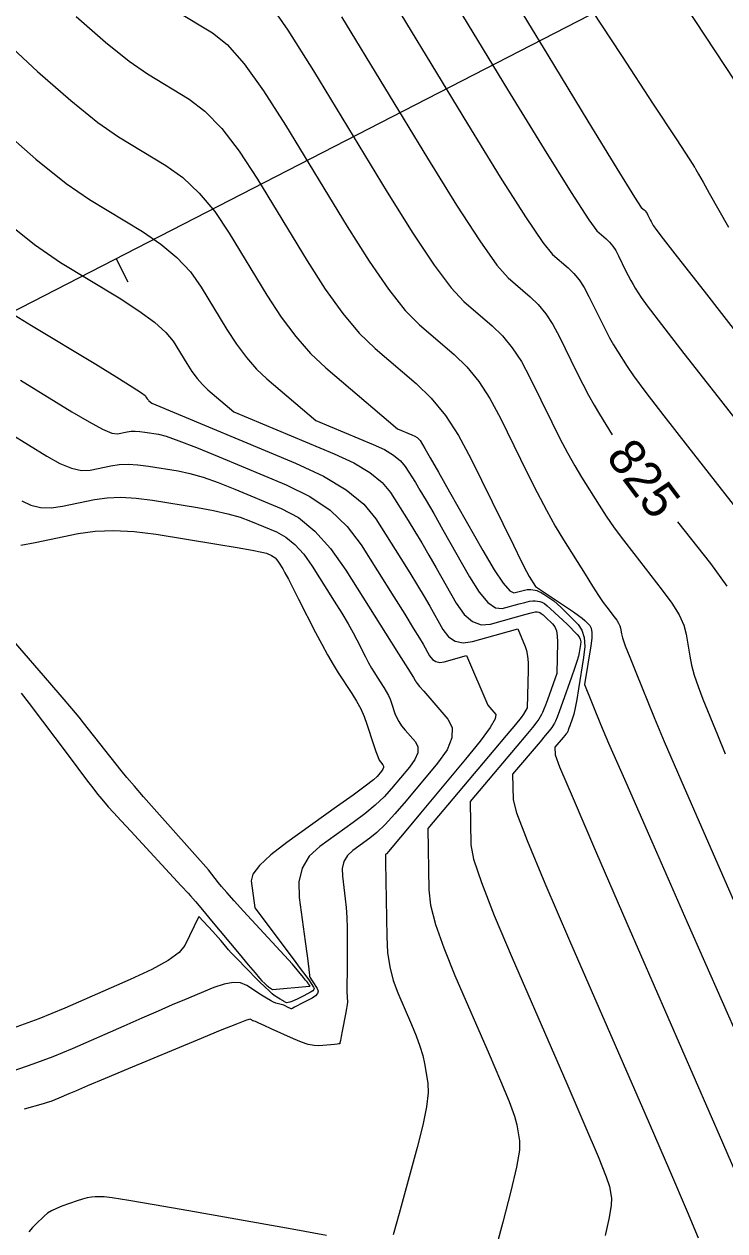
# Model space of a CAD drawing. Extents: x 1715724 to 1716561, y 394063 to 395906.
# Drawn here: x 1716008.73 to 1716035.77, y 394999.44 to 395046.03 of the extents above; entities that cross this region are included whole.
import ezdxf

# ---------------------------------------------------------------- set-up
doc = ezdxf.new("R2010")
doc.units = 0
for name, color, linetype in [('DT_X_Contour_Major', 7, 'Continuous'), ('DT_X_Contour_Minor', 7, 'Continuous'), ('GE_P_CL_10', 7, 'Continuous')]:
    doc.layers.add(name, color=color, linetype=linetype)

msp = doc.modelspace()

# ---------------------------------------------------------------- linework, layer by layer
at = {"layer": 'DT_X_Contour_Major'}
for points in [[(1716033.841, 395047.347), (1716036.153, 395043.821)], [(1716020.981, 395046.306), (1716024.291, 395040.859), (1716025.416, 395039.037), (1716026.311, 395037.658), (1716026.976, 395036.722), (1716027.41, 395036.229), (1716028.259, 395035.503), (1716028.569, 395035.203), (1716028.86, 395034.844), (1716029.133, 395034.427), (1716029.389, 395033.953), (1716030.046, 395032.611), (1716030.286, 395032.131), (1716030.513, 395031.698), (1716030.729, 395031.313), (1716030.932, 395030.974), (1716031.428, 395030.179)], [(1716007.741, 395042.079), (1716009.181, 395040.818), (1716010.351, 395039.875), (1716011.251, 395039.252), (1716013.293, 395038.016), (1716014.009, 395037.534), (1716014.626, 395037.016), (1716015.145, 395036.461), (1716015.564, 395035.87), (1716016.552, 395034.245), (1716016.926, 395033.668), (1716017.309, 395033.158), (1716017.7, 395032.714), (1716018.099, 395032.337), (1716019.981, 395030.73), (1716022.198, 395029.805), (1716022.632, 395029.603), (1716022.983, 395029.393), (1716023.253, 395029.174), (1716023.439, 395028.946), (1716023.828, 395028.329), (1716024.003, 395028.042), (1716024.239, 395027.642), (1716024.535, 395027.13), (1716024.891, 395026.506), (1716025.921, 395024.692), (1716026.289, 395024.105), (1716026.622, 395023.706), (1716026.919, 395023.493), (1716027.181, 395023.468), (1716027.831, 395023.649), (1716028.053, 395023.707), (1716028.231, 395023.746), (1716028.365, 395023.765), (1716028.455, 395023.765), (1716028.637, 395023.739), (1716028.714, 395023.714), (1716028.807, 395023.66), (1716028.918, 395023.575), (1716029.046, 395023.462), (1716029.683, 395022.861), (1716030.072, 395022.468), (1716030.143, 395022.38), (1716030.188, 395022.285), (1716030.208, 395022.183), (1716030.202, 395022.074), (1716030.153, 395021.774), (1716030.121, 395021.63), (1716030.06, 395021.422), (1716029.971, 395021.152), (1716029.854, 395020.818), (1716029.503, 395019.843), (1716029.385, 395019.519), (1716029.294, 395019.276), (1716029.231, 395019.116), (1716029.196, 395019.038), (1716029.138, 395018.938), (1716029.091, 395018.871), (1716028.992, 395018.747), (1716028.842, 395018.565), (1716028.64, 395018.324), (1716027.58, 395017.068), (1716027.596, 395016.078), (1716027.735, 395015.58), (1716028.145, 395014.51), (1716028.826, 395012.868), (1716029.778, 395010.655), (1716032.678, 395003.989), (1716033.631, 395001.789), (1716034.318, 395000.186), (1716034.738, 394999.181)], [(1716008.645, 395027.622), (1716008.985, 395027.46), (1716009.36, 395027.371), (1716009.77, 395027.357), (1716010.215, 395027.416), (1716011.447, 395027.672), (1716011.933, 395027.742), (1716012.467, 395027.762), (1716013.048, 395027.731), (1716013.678, 395027.65), (1716015.42, 395027.365), (1716016.038, 395027.251), (1716016.586, 395027.126), (1716017.064, 395026.989), (1716017.471, 395026.84), (1716018.464, 395026.427), (1716018.829, 395026.228), (1716019.181, 395025.941), (1716019.519, 395025.567), (1716019.844, 395025.106), (1716020.692, 395023.758), (1716020.985, 395023.285), (1716021.23, 395022.878), (1716021.426, 395022.536), (1716021.574, 395022.26), (1716021.903, 395021.609), (1716022.023, 395021.377), (1716022.138, 395021.168), (1716022.246, 395020.982), (1716022.348, 395020.82), (1716022.613, 395020.417), (1716022.706, 395020.266), (1716022.786, 395020.116), (1716022.854, 395019.966), (1716022.908, 395019.817), (1716023.037, 395019.42), (1716023.098, 395019.268), (1716023.184, 395019.11), (1716023.295, 395018.946), (1716023.431, 395018.776), (1716023.827, 395018.316), (1716023.924, 395018.126), (1716023.919, 395017.901), (1716023.813, 395017.642), (1716023.604, 395017.348), (1716022.911, 395016.516), (1716022.624, 395016.2), (1716022.281, 395015.876), (1716021.882, 395015.544), (1716021.428, 395015.203), (1716020.143, 395014.285), (1716019.732, 395013.903), (1716019.462, 395013.449), (1716019.334, 395012.921), (1716019.348, 395012.319), (1716019.573, 395010.618), (1716019.646, 395010.058), (1716019.699, 395009.656), (1716019.731, 395009.412), (1716019.741, 395009.324), (1716019.741, 395009.302), (1716019.741, 395009.293), (1716019.741, 395009.286), (1716019.742, 395009.279), (1716019.744, 395009.273), (1716019.748, 395009.257), (1716019.757, 395009.24), (1716019.781, 395009.2), (1716019.821, 395009.137), (1716019.875, 395009.052), (1716020.041, 395008.794), (1716020.076, 395008.699), (1716020.054, 395008.606), (1716019.975, 395008.517), (1716019.841, 395008.431), (1716019.408, 395008.205), (1716019.265, 395008.13), (1716019.161, 395008.076), (1716019.095, 395008.042), (1716019.068, 395008.028), (1716019.047, 395008.019), (1716019.034, 395008.018), (1716019.013, 395008.025), (1716018.984, 395008.037), (1716018.945, 395008.057), (1716018.746, 395008.163), (1716018.44, 395008.239), (1716018.356, 395008.27), (1716018.236, 395008.332), (1716018.079, 395008.424), (1716017.886, 395008.547), (1716017.322, 395008.915), (1716017.084, 395009.013), (1716016.792, 395009.032), (1716016.447, 395008.973), (1716016.047, 395008.835), (1716014.912, 395008.361), (1716014.446, 395008.165), (1716013.901, 395007.931), (1716013.275, 395007.659), (1716012.571, 395007.351), (1716010.585, 395006.477), (1716009.833, 395006.162), (1716009.068, 395005.873), (1716008.289, 395005.609)], [(1716033.949, 395026.821), (1716035.212, 395025.209), (1716035.852, 395024.335)]]:
    msp.add_lwpolyline(points, dxfattribs=at)
at = {"layer": 'DT_X_Contour_Minor'}
for points in [[(1716024.232, 395052.568), (1716028.934, 395044.827), (1716030.482, 395042.282), (1716031.6, 395040.455), (1716032.288, 395039.344), (1716032.545, 395038.949), (1716032.656, 395038.854), (1716032.697, 395038.815), (1716032.735, 395038.768), (1716032.771, 395038.713), (1716032.805, 395038.651), (1716032.891, 395038.474), (1716032.922, 395038.411), (1716032.952, 395038.354), (1716032.981, 395038.304), (1716033.007, 395038.259), (1716033.076, 395038.149), (1716033.304, 395037.851), (1716033.934, 395037.04), (1716034.968, 395035.716), (1716036.405, 395033.88)], [(1716023.148, 395050.481), (1716027.386, 395043.504), (1716028.794, 395041.201), (1716029.837, 395039.522), (1716030.517, 395038.47), (1716030.833, 395038.043), (1716031.191, 395037.737), (1716031.321, 395037.611), (1716031.443, 395037.46), (1716031.559, 395037.284), (1716031.666, 395037.085), (1716031.942, 395036.52), (1716032.044, 395036.318), (1716032.139, 395036.136), (1716032.23, 395035.973), (1716032.316, 395035.831), (1716032.537, 395035.477), (1716032.776, 395035.148), (1716033.327, 395034.427), (1716034.191, 395033.313), (1716035.367, 395031.807), (1716038.921, 395027.269)], [(1716028.03, 395050.528), (1716031.779, 395044.813), (1716033.01, 395042.937), (1716033.89, 395041.594), (1716034.42, 395040.786), (1716034.6, 395040.511), (1716034.611, 395040.49), (1716034.65, 395040.422), (1716034.756, 395040.234), (1716034.93, 395039.925), (1716035.172, 395039.496), (1716035.907, 395038.19)], [(1716022.065, 395048.394), (1716025.838, 395042.181), (1716027.105, 395040.119), (1716028.074, 395038.59), (1716028.746, 395037.596), (1716029.121, 395037.136), (1716029.725, 395036.62), (1716029.945, 395036.407), (1716030.152, 395036.152), (1716030.346, 395035.856), (1716030.527, 395035.519), (1716030.994, 395034.565), (1716031.165, 395034.225), (1716031.326, 395033.917), (1716031.479, 395033.643), (1716031.624, 395033.402), (1716031.997, 395032.805), (1716032.247, 395032.445), (1716032.72, 395031.813), (1716033.414, 395030.91), (1716034.329, 395029.735), (1716037.066, 395026.239)], [(1716018.08, 395046.985), (1716018.91, 395045.789), (1716019.898, 395044.219), (1716022.743, 395039.536), (1716023.728, 395037.955), (1716024.548, 395036.726), (1716025.205, 395035.848), (1716025.698, 395035.322), (1716026.793, 395034.387), (1716027.193, 395033.999), (1716027.568, 395033.536), (1716027.921, 395032.999), (1716028.25, 395032.387), (1716029.097, 395030.657), (1716029.407, 395030.038), (1716029.701, 395029.48), (1716029.978, 395028.982), (1716030.24, 395028.545), (1716030.917, 395027.461), (1716031.191, 395027.039), (1716031.505, 395026.586), (1716031.859, 395026.103), (1716032.253, 395025.59), (1716033.357, 395024.179), (1716033.726, 395023.677), (1716034.003, 395023.226), (1716034.189, 395022.828), (1716034.283, 395022.483), (1716034.414, 395021.63), (1716034.483, 395021.287), (1716034.592, 395020.894), (1716034.74, 395020.453), (1716034.928, 395019.964), (1716035.483, 395018.593), (1716035.789, 395017.864)], [(1716014.616, 395046.532), (1716015.995, 395045.697), (1716016.559, 395045.24), (1716017.217, 395044.493), (1716017.969, 395043.457), (1716018.814, 395042.132), (1716021.195, 395038.213), (1716022.039, 395036.873), (1716022.786, 395035.794), (1716023.435, 395034.974), (1716023.986, 395034.415), (1716025.328, 395033.27), (1716025.816, 395032.795), (1716026.277, 395032.228), (1716026.708, 395031.57), (1716027.112, 395030.821), (1716028.149, 395028.702), (1716028.528, 395027.944), (1716028.888, 395027.261), (1716029.228, 395026.652), (1716029.548, 395026.117), (1716030.377, 395024.789), (1716030.663, 395024.336), (1716030.898, 395023.973), (1716031.082, 395023.7), (1716031.215, 395023.517), (1716031.503, 395023.15), (1716031.599, 395023.019), (1716031.671, 395022.901), (1716031.719, 395022.798), (1716031.744, 395022.708), (1716031.778, 395022.486), (1716031.822, 395022.331), (1716031.93, 395022.033), (1716032.1, 395021.593), (1716032.334, 395021.009), (1716033.042, 395019.262), (1716033.432, 395018.332), (1716034.07, 395016.85), (1716034.957, 395014.818), (1716036.092, 395012.234)], [(1716010.743, 395046.321), (1716011.872, 395045.332), (1716012.789, 395044.594), (1716013.495, 395044.105), (1716015.094, 395043.137), (1716015.709, 395042.671), (1716016.353, 395042.001), (1716017.027, 395041.125), (1716017.731, 395040.045), (1716019.647, 395036.89), (1716020.35, 395035.792), (1716021.023, 395034.862), (1716021.664, 395034.101), (1716022.275, 395033.508), (1716023.862, 395032.153), (1716024.44, 395031.591), (1716024.985, 395030.92), (1716025.496, 395030.142), (1716025.973, 395029.255), (1716027.2, 395026.748), (1716027.609, 395025.915), (1716027.916, 395025.296), (1716028.121, 395024.892), (1716028.223, 395024.703), (1716028.461, 395024.321), (1716029.695, 395023.501), (1716029.935, 395023.338), (1716030.127, 395023.201), (1716030.271, 395023.09), (1716030.366, 395023.004), (1716030.557, 395022.812), (1716030.613, 395022.709), (1716030.638, 395022.544), (1716030.633, 395022.318), (1716030.596, 395022.029), (1716030.354, 395020.539), (1716030.978, 395018.999), (1716031.287, 395018.275), (1716031.944, 395016.766), (1716032.952, 395014.47), (1716034.308, 395011.387), (1716038.391, 395002.119)], [(1716007.717, 395045.61), (1716009.242, 395044.2), (1716010.526, 395043.075), (1716011.57, 395042.234), (1716012.373, 395041.679), (1716014.194, 395040.576), (1716014.859, 395040.103), (1716015.49, 395039.508), (1716016.086, 395038.793), (1716016.648, 395037.957), (1716018.099, 395035.567), (1716018.65, 395034.72), (1716019.213, 395033.97), (1716019.787, 395033.317), (1716020.374, 395032.762), (1716023.142, 395030.399), (1716023.698, 395030.167), (1716023.807, 395030.117), (1716023.895, 395030.064), (1716023.962, 395030.009), (1716024.009, 395029.952), (1716024.107, 395029.797), (1716024.199, 395029.64), (1716024.403, 395029.285), (1716024.719, 395028.731), (1716025.146, 395027.979), (1716026.435, 395025.709), (1716026.872, 395024.968), (1716027.217, 395024.448), (1716027.469, 395024.149), (1716027.63, 395024.07), (1716027.934, 395024.155), (1716028.042, 395024.182), (1716028.137, 395024.198), (1716028.219, 395024.204), (1716028.288, 395024.201), (1716028.455, 395024.176), (1716028.522, 395024.16), (1716028.599, 395024.129), (1716028.686, 395024.083), (1716028.783, 395024.023), (1716029.054, 395023.843), (1716029.166, 395023.761), (1716029.297, 395023.65), (1716029.449, 395023.509), (1716029.621, 395023.34), (1716030.106, 395022.851), (1716030.256, 395022.633), (1716030.342, 395022.348), (1716030.364, 395021.996), (1716030.322, 395021.576), (1716030.125, 395020.365), (1716030.055, 395019.954), (1716029.994, 395019.629), (1716029.942, 395019.39), (1716029.898, 395019.237), (1716029.793, 395018.945), (1716029.757, 395018.847), (1716029.73, 395018.774), (1716029.711, 395018.726), (1716029.701, 395018.703), (1716029.683, 395018.673), (1716029.669, 395018.653), (1716029.64, 395018.615), (1716029.594, 395018.561), (1716029.534, 395018.488), (1716029.215, 395018.111), (1716029.22, 395017.814), (1716029.394, 395017.361), (1716029.913, 395016.129), (1716030.778, 395014.118), (1716031.989, 395011.328), (1716035.677, 395002.85), (1716036.889, 395000.062)], [(1716007.835, 395038.56), (1716009.132, 395037.516), (1716010.13, 395036.825), (1716012.392, 395035.456), (1716013.159, 395034.966), (1716013.763, 395034.524), (1716014.203, 395034.129), (1716014.481, 395033.783), (1716015.004, 395032.922), (1716015.202, 395032.617), (1716015.405, 395032.346), (1716015.612, 395032.111), (1716015.823, 395031.911), (1716016.82, 395031.06), (1716020.698, 395029.444), (1716021.457, 395029.09), (1716022.072, 395028.721), (1716022.543, 395028.339), (1716022.87, 395027.941), (1716023.549, 395026.861), (1716023.808, 395026.443), (1716024.075, 395025.999), (1716024.352, 395025.529), (1716024.636, 395025.033), (1716025.407, 395023.675), (1716025.707, 395023.243), (1716026.027, 395022.964), (1716026.369, 395022.838), (1716026.732, 395022.865), (1716027.728, 395023.143), (1716028.058, 395023.233), (1716028.301, 395023.297), (1716028.457, 395023.334), (1716028.526, 395023.343), (1716028.594, 395023.333), (1716028.629, 395023.318), (1716028.683, 395023.28), (1716028.756, 395023.219), (1716028.848, 395023.134), (1716029.119, 395022.879), (1716029.207, 395022.763), (1716029.269, 395022.606), (1716029.304, 395022.408), (1716029.313, 395022.169), (1716029.291, 395020.961), (1716028.923, 395019.938), (1716028.849, 395019.738), (1716028.786, 395019.578), (1716028.733, 395019.456), (1716028.691, 395019.373), (1716028.593, 395019.203), (1716028.513, 395019.09), (1716028.345, 395018.879), (1716028.09, 395018.569), (1716027.747, 395018.16), (1716025.944, 395016.024), (1716025.972, 395014.342), (1716026.076, 395013.799), (1716026.376, 395012.891), (1716026.873, 395011.619), (1716027.567, 395009.982), (1716029.678, 395005.129), (1716030.374, 395003.515), (1716030.88, 395002.315), (1716031.195, 395001.527), (1716031.319, 395001.152), (1716031.396, 395000.703), (1716031.388, 395000.432), (1716031.305, 394999.954), (1716031.148, 394999.271)], [(1716008.182, 395034.903), (1716009.008, 395034.399), (1716011.491, 395032.895), (1716012.309, 395032.397), (1716012.899, 395032.031), (1716013.262, 395031.797), (1716013.397, 395031.695), (1716013.456, 395031.599), (1716013.478, 395031.565), (1716013.501, 395031.535), (1716013.524, 395031.508), (1716013.548, 395031.486), (1716013.659, 395031.391), (1716019.198, 395029.082), (1716020.282, 395028.576), (1716021.161, 395028.05), (1716021.833, 395027.503), (1716022.3, 395026.935), (1716023.27, 395025.393), (1716023.612, 395024.845), (1716023.912, 395024.356), (1716024.168, 395023.928), (1716024.381, 395023.56), (1716024.893, 395022.659), (1716025.108, 395022.376), (1716025.369, 395022.204), (1716025.675, 395022.143), (1716026.028, 395022.192), (1716027.78, 395022.68), (1716028.068, 395022.008), (1716028.121, 395021.842), (1716028.157, 395021.635), (1716028.176, 395021.386), (1716028.177, 395021.094), (1716028.145, 395019.635), (1716028.004, 395019.392), (1716027.91, 395019.266), (1716027.687, 395018.991), (1716027.334, 395018.568), (1716026.854, 395017.996), (1716024.309, 395014.981), (1716024.347, 395012.606), (1716024.416, 395012.018), (1716024.608, 395011.273), (1716024.921, 395010.369), (1716025.356, 395009.308), (1716026.678, 395006.268), (1716027.117, 395005.242), (1716027.442, 395004.444), (1716027.652, 395003.874), (1716027.749, 395003.531), (1716027.853, 395002.923), (1716027.842, 395002.555), (1716027.73, 395001.907), (1716027.517, 395000.981), (1716027.203, 394999.775), (1716026.233, 394996.186)], [(1716008.59, 395032.286), (1716010.569, 395031.067), (1716011.236, 395030.671), (1716011.753, 395030.396), (1716012.119, 395030.243), (1716012.335, 395030.211), (1716012.709, 395030.289), (1716012.857, 395030.31), (1716013.019, 395030.316), (1716013.196, 395030.307), (1716013.388, 395030.282), (1716013.918, 395030.195), (1716014.213, 395030.116), (1716014.701, 395029.944), (1716015.382, 395029.679), (1716016.256, 395029.321), (1716018.843, 395028.243), (1716019.752, 395027.795), (1716020.535, 395027.26), (1716021.195, 395026.638), (1716021.73, 395025.93), (1716022.991, 395023.925), (1716023.417, 395023.246), (1716023.748, 395022.714), (1716023.985, 395022.327), (1716024.127, 395022.087), (1716024.379, 395021.642), (1716024.486, 395021.502), (1716024.614, 395021.417), (1716024.766, 395021.387), (1716024.94, 395021.411), (1716025.806, 395021.652), (1716026.623, 395019.741), (1716026.936, 395019.377), (1716026.913, 395019.212), (1716026.71, 395018.87), (1716026.328, 395018.352), (1716025.767, 395017.658), (1716024.03, 395015.573), (1716023.458, 395014.888), (1716023.048, 395014.397), (1716022.798, 395014.1), (1716022.71, 395013.997), (1716022.687, 395013.981), (1716022.679, 395013.974), (1716022.675, 395013.966), (1716022.672, 395013.956), (1716022.673, 395013.946), (1716022.677, 395013.915), (1716022.678, 395013.901), (1716022.679, 395013.882), (1716022.679, 395013.858), (1716022.679, 395013.829), (1716022.678, 395013.681), (1716022.724, 395010.793), (1716022.758, 395010.194), (1716022.839, 395009.635), (1716022.968, 395009.115), (1716023.145, 395008.635), (1716023.679, 395007.407), (1716023.86, 395006.969), (1716024.004, 395006.573), (1716024.11, 395006.22), (1716024.178, 395005.91), (1716024.31, 395005.142), (1716024.321, 395004.77), (1716024.255, 395004.232), (1716024.112, 395003.528), (1716023.892, 395002.657), (1716023.204, 395000.112), (1716022.967, 394999.291)], [(1716008.187, 395030.22), (1716009.607, 395029.344), (1716010.111, 395029.065), (1716010.556, 395028.884), (1716010.944, 395028.8), (1716011.275, 395028.813), (1716012.078, 395028.98), (1716012.395, 395029.026), (1716012.743, 395029.039), (1716013.122, 395029.019), (1716013.533, 395028.966), (1716014.669, 395028.78), (1716015.126, 395028.684), (1716015.644, 395028.535), (1716016.223, 395028.334), (1716016.864, 395028.081), (1716018.654, 395027.335), (1716019.313, 395026.976), (1716019.947, 395026.459), (1716020.557, 395025.784), (1716021.143, 395024.952), (1716022.672, 395022.521), (1716023.174, 395021.723), (1716023.533, 395021.151), (1716023.75, 395020.806), (1716023.824, 395020.687), (1716023.832, 395020.672), (1716023.835, 395020.666), (1716023.837, 395020.662), (1716023.84, 395020.657), (1716023.842, 395020.653), (1716023.848, 395020.644), (1716023.851, 395020.641), (1716023.852, 395020.637), (1716023.854, 395020.634), (1716023.855, 395020.63), (1716023.858, 395020.621), (1716023.892, 395020.58), (1716023.99, 395020.464), (1716024.153, 395020.274), (1716024.381, 395020.009), (1716025.076, 395019.202), (1716025.247, 395018.869), (1716025.239, 395018.474), (1716025.051, 395018.019), (1716024.685, 395017.503), (1716023.47, 395016.045), (1716023.041, 395015.544), (1716022.664, 395015.137), (1716022.34, 395014.822), (1716022.069, 395014.6), (1716021.415, 395014.133), (1716021.206, 395013.939), (1716021.068, 395013.707), (1716021.003, 395013.438), (1716021.01, 395013.132), (1716021.125, 395012.267), (1716021.162, 395011.923), (1716021.187, 395011.542), (1716021.2, 395011.123), (1716021.202, 395010.667), (1716021.191, 395009.399), (1716021.188, 395008.981), (1716021.187, 395008.675), (1716021.19, 395008.482), (1716021.194, 395008.402), (1716021.211, 395008.34), (1716021.21, 395008.289), (1716021.197, 395008.183), (1716021.17, 395008.022), (1716021.129, 395007.806), (1716021.005, 395007.156), (1716020.963, 395006.942), (1716020.933, 395006.79), (1716020.915, 395006.697), (1716020.907, 395006.666), (1716020.903, 395006.662), (1716020.88, 395006.659), (1716020.816, 395006.653), (1716020.709, 395006.643), (1716020.56, 395006.631), (1716020.108, 395006.593), (1716019.919, 395006.598), (1716019.693, 395006.644), (1716019.429, 395006.73), (1716019.126, 395006.856), (1716018.269, 395007.246), (1716017.987, 395007.374), (1716017.781, 395007.467), (1716017.653, 395007.524), (1716017.602, 395007.545), (1716017.568, 395007.553), (1716017.554, 395007.557), (1716017.539, 395007.564), (1716017.522, 395007.573), (1716017.504, 395007.585), (1716017.452, 395007.618), (1716017.31, 395007.577), (1716016.923, 395007.429), (1716016.291, 395007.173), (1716015.413, 395006.809), (1716012.746, 395005.697), (1716011.853, 395005.324), (1716011.173, 395005.039), (1716010.706, 395004.843), (1716010.454, 395004.734), (1716010.064, 395004.563), (1716009.917, 395004.501), (1716009.766, 395004.444), (1716009.614, 395004.393), (1716009.458, 395004.346), (1716008.726, 395004.139)], [(1716008.596, 395025.914), (1716009.155, 395026.018), (1716010.816, 395026.363), (1716011.471, 395026.458), (1716012.19, 395026.485), (1716012.974, 395026.444), (1716013.823, 395026.334), (1716016.171, 395025.949), (1716016.951, 395025.819), (1716017.529, 395025.718), (1716017.905, 395025.644), (1716018.079, 395025.6), (1716018.274, 395025.519), (1716018.346, 395025.479), (1716018.415, 395025.423), (1716018.481, 395025.35), (1716018.545, 395025.259), (1716018.711, 395024.995), (1716018.796, 395024.848), (1716018.927, 395024.605), (1716019.103, 395024.266), (1716019.324, 395023.832), (1716019.974, 395022.547), (1716020.212, 395022.088), (1716020.438, 395021.675), (1716020.652, 395021.307), (1716020.854, 395020.986), (1716021.378, 395020.19), (1716021.561, 395019.892), (1716021.72, 395019.595), (1716021.853, 395019.299), (1716021.961, 395019.004), (1716022.216, 395018.218), (1716022.304, 395017.955), (1716022.377, 395017.755), (1716022.436, 395017.618), (1716022.48, 395017.544), (1716022.577, 395017.431), (1716022.601, 395017.384), (1716022.6, 395017.329), (1716022.574, 395017.265), (1716022.523, 395017.192), (1716022.352, 395016.988), (1716022.206, 395016.856), (1716021.897, 395016.616), (1716021.424, 395016.266), (1716020.787, 395015.807), (1716018.871, 395014.437), (1716018.246, 395013.959), (1716017.808, 395013.554), (1716017.557, 395013.22), (1716017.493, 395012.96), (1716017.632, 395011.911), (1716019.106, 395009.946), (1716019.387, 395009.571), (1716019.597, 395009.288), (1716019.737, 395009.097), (1716019.806, 395008.998), (1716019.897, 395008.856), (1716019.917, 395008.804), (1716019.908, 395008.755), (1716019.87, 395008.709), (1716019.802, 395008.665), (1716019.503, 395008.51), (1716019.423, 395008.469), (1716019.344, 395008.431), (1716019.266, 395008.394), (1716019.058, 395008.299), (1716018.986, 395008.27), (1716018.924, 395008.254), (1716018.873, 395008.252), (1716018.833, 395008.264), (1716018.741, 395008.313), (1716018.703, 395008.334), (1716018.607, 395008.392), (1716018.549, 395008.429), (1716018.385, 395008.535), (1716018.304, 395008.598), (1716018.182, 395008.706), (1716018.021, 395008.861), (1716017.819, 395009.061), (1716017.228, 395009.655), (1716017.024, 395009.862), (1716016.855, 395010.038), (1716016.721, 395010.183), (1716016.621, 395010.297), (1716016.404, 395010.558), (1716016.318, 395010.659), (1716016.224, 395010.767), (1716016.121, 395010.881), (1716016.011, 395011.001), (1716015.475, 395011.58), (1716014.935, 395010.456), (1716014.716, 395010.193), (1716014.29, 395009.887), (1716013.657, 395009.538), (1716012.818, 395009.145), (1716010.304, 395008.039), (1716009.299, 395007.625), (1716008.169, 395007.214)], [(1716011.023, 395019.061), (1716010.847, 395019.276), (1716010.572, 395019.604), (1716010.197, 395020.045), (1716009.721, 395020.599), (1716008.319, 395022.225)], [(1716008.617, 395020.198), (1716008.921, 395019.797), (1716010.425, 395017.801), (1716011.173, 395016.807), (1716011.323, 395016.61), (1716011.452, 395016.443), (1716011.56, 395016.306), (1716011.648, 395016.199), (1716011.854, 395015.955), (1716011.974, 395015.819), (1716012.179, 395015.593), (1716012.469, 395015.277), (1716012.845, 395014.871), (1716014.796, 395012.765), (1716015.055, 395012.486), (1716015.153, 395012.374), (1716015.337, 395012.158), (1716015.607, 395011.837), (1716015.962, 395011.412), (1716017.022, 395010.14), (1716017.375, 395009.718), (1716017.64, 395009.404), (1716017.815, 395009.198), (1716017.902, 395009.102), (1716018.014, 395008.989), (1716018.055, 395008.949), (1716018.093, 395008.915), (1716018.13, 395008.885), (1716018.164, 395008.861), (1716018.318, 395008.761), (1716019.741, 395008.888), (1716019.754, 395008.894), (1716019.756, 395008.895), (1716019.758, 395008.896), (1716019.76, 395008.897), (1716019.761, 395008.898), (1716019.764, 395008.899), (1716019.764, 395008.899), (1716019.765, 395008.9), (1716019.765, 395008.9), (1716019.765, 395008.901), (1716019.764, 395008.903), (1716019.762, 395008.905), (1716019.757, 395008.911), (1716019.75, 395008.921), (1716019.74, 395008.935), (1716019.709, 395008.976), (1716019.687, 395009.003), (1716019.646, 395009.054), (1716019.585, 395009.128), (1716019.505, 395009.226), (1716019.084, 395009.736), (1716017.201, 395011.789), (1716016.838, 395012.187), (1716016.554, 395012.502), (1716016.351, 395012.734), (1716016.228, 395012.883), (1716015.839, 395013.384), (1716013.749, 395015.734), (1716013.334, 395016.204), (1716012.984, 395016.607), (1716012.699, 395016.944), (1716012.48, 395017.215), (1716011.023, 395019.061)], [(1716020.398, 394999.26), (1716019.076, 394999.507), (1716015.082, 395000.218), (1716013.754, 395000.451), (1716012.769, 395000.618), (1716012.125, 395000.719), (1716011.823, 395000.754), (1716011.473, 395000.758), (1716011.331, 395000.75), (1716011.166, 395000.722), (1716010.979, 395000.673), (1716010.77, 395000.605), (1716010.182, 395000.396), (1716009.974, 395000.313), (1716009.791, 395000.222), (1716009.633, 395000.121), (1716009.499, 395000.012), (1716009.177, 394999.708), (1716009.049, 394999.574), (1716008.907, 394999.401)]]:
    msp.add_lwpolyline(points, dxfattribs=at)
at = {"layer": 'GE_P_CL_10'}
for p, q in [((1716111.51, 395088.045), (1715997.389, 395029.305)), ((1716012.276, 395036.967), (1716012.733, 395036.078))]:
    msp.add_line(p, q, dxfattribs=at)

# ---------------------------------------------------------------- texts
at = {"layer": 'DT_X_Contour_Major'}
msp.add_text('825', height=1.4, rotation=306.9045, dxfattribs=at).set_placement((1716031.149, 395029.322))

doc.saveas('drawing.dxf')
